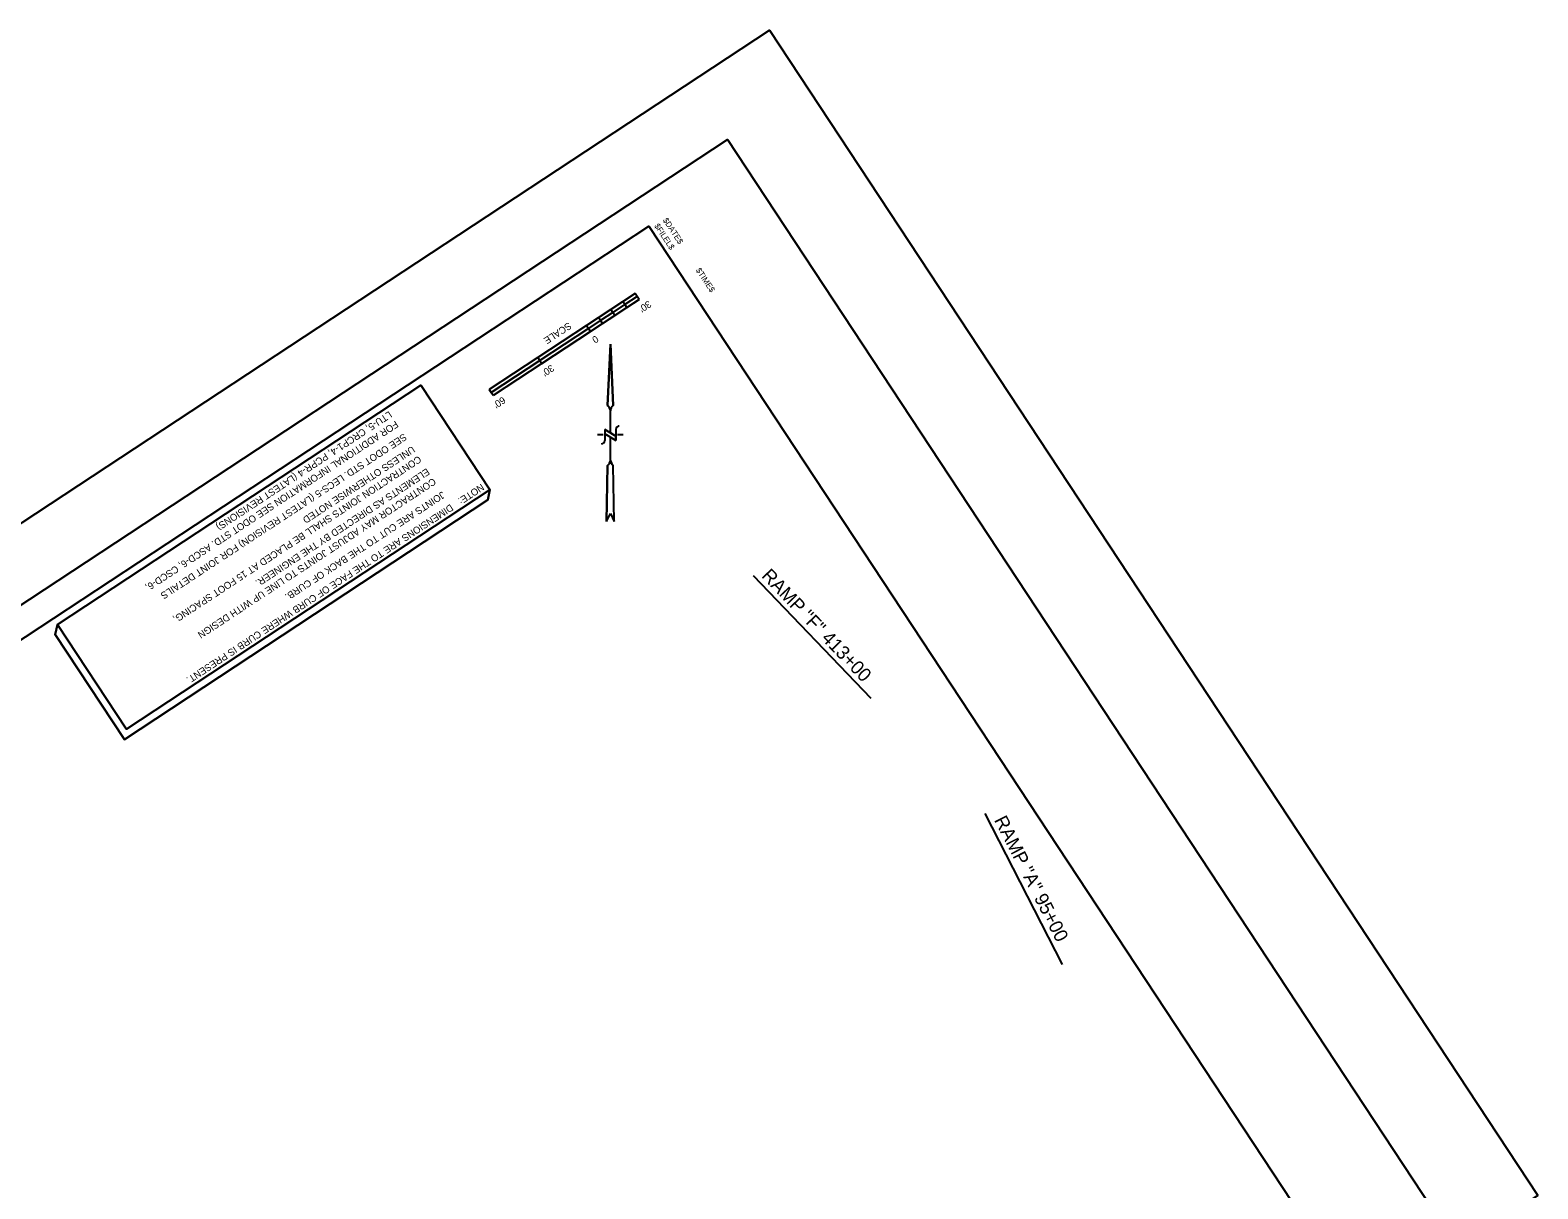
# Model space of a CAD drawing. Extents: x 2149232 to 2150530, y 142725 to 143920.
# Drawn here: x 2149753 to 2150530, y 143323 to 143920 of the extents above; entities that cross this region are included whole.
import ezdxf

# ---------------------------------------------------------------- set-up
doc = ezdxf.new("R2010")
doc.units = 0
for name, color, linetype in [('EX_Align_8_Leader', 7, 'Continuous'), ('PR_Align_1_Leader', 7, 'Continuous'), ('PR_Align_1_PI_Curve', 7, 'Continuous'), ('PR_Align_Ramp_A_PI_Curve', 7, 'Continuous'), ('PR_Align_Ramp_B_PC', 7, 'Continuous'), ('PR_Align_Ramp_B_PI', 7, 'Continuous'), ('PR_Align_Ramp_G', 7, 'Continuous'), ('PR_Align_Ramp_G_Leader', 7, 'Continuous'), ('PR_Align_Ramp_G_Txt', 7, 'Continuous')]:
    doc.layers.add(name, color=color, linetype=linetype)

msp = doc.modelspace()

# ---------------------------------------------------------------- linework, layer by layer
at = {"layer": 'EX_Align_8_Leader'}
for p, q in [((2150186.46, 143575.67), (2150125.85, 143638.92)), ((2150285.2, 143438.35), (2150245.3, 143516.34))]:
    msp.add_line(p, q, dxfattribs=at)
at = {"layer": 'PR_Align_1_PI_Curve'}
msp.add_lwpolyline([(2149989.95, 143683.24), (2149802.55, 143559.77), (2149766.96, 143613.78), (2149954.36, 143737.25)], close=True, dxfattribs=at)
msp.add_lwpolyline([(2149989.95, 143683.24), (2149988.88, 143678.05), (2149801.48, 143554.57), (2149765.89, 143608.59), (2149766.96, 143613.78)], dxfattribs=at)
at = {"layer": 'PR_Align_Ramp_A_PI_Curve'}
msp.add_lwpolyline([(2150475.65, 143312.82), (2149623.91, 142751.63), (2149260.79, 143302.75), (2150112.52, 143863.95)], close=True, dxfattribs=at)
at = {"layer": 'PR_Align_Ramp_B_PC'}
for p, q in [((2150064.81, 143784.61), (2149989.65, 143735.09)), ((2150066.87, 143781.48), (2150064.81, 143784.61)), ((2150066.87, 143781.48), (2149991.72, 143731.96)), ((2150058.54, 143780.48), (2150052.28, 143776.35)), ((2150054.34, 143773.22), (2150052.28, 143776.35)), ((2150054.34, 143773.22), (2150052.28, 143776.35)), ((2150052.28, 143776.35), (2150053.31, 143774.79)), ((2150059.57, 143778.92), (2150053.31, 143774.79)), ((2150053.31, 143774.79), (2150059.57, 143778.92)), ((2150060.61, 143777.35), (2150058.54, 143780.48)), ((2150059.57, 143778.92), (2150058.54, 143780.48)), ((2150065.84, 143783.04), (2150059.57, 143778.92)), ((2150065.84, 143783.04), (2150059.57, 143778.92)), ((2150059.57, 143778.92), (2150060.61, 143777.35)), ((2150060.61, 143777.35), (2150066.87, 143781.48)), ((2150066.87, 143781.48), (2150065.84, 143783.04)), ((2150046.02, 143772.23), (2150039.75, 143768.1)), ((2150047.05, 143770.66), (2150040.79, 143766.54)), ((2150040.79, 143766.54), (2150047.05, 143770.66)), ((2150048.08, 143769.1), (2150046.02, 143772.23)), ((2150047.05, 143770.66), (2150046.02, 143772.23)), ((2150053.31, 143774.79), (2150047.05, 143770.66)), ((2150053.31, 143774.79), (2150047.05, 143770.66)), ((2150047.05, 143770.66), (2150048.08, 143769.1)), ((2150048.08, 143769.1), (2150054.34, 143773.22)), ((2150054.34, 143773.22), (2150053.31, 143774.79)), ((2150040.79, 143766.54), (2149990.68, 143733.52)), ((2150040.79, 143766.54), (2150015.74, 143750.03)), ((2150016.77, 143748.46), (2150041.82, 143764.97)), ((2150039.75, 143768.1), (2150040.79, 143766.54)), ((2150039.75, 143768.1), (2150040.79, 143766.54)), ((2150040.79, 143766.54), (2150041.82, 143764.97)), ((2150041.82, 143764.97), (2150040.79, 143766.54)), ((2150014.7, 143751.6), (2149989.65, 143735.09)), ((2149990.68, 143733.52), (2150015.74, 143750.03)), ((2150014.7, 143751.6), (2150015.74, 143750.03)), ((2150015.74, 143750.03), (2150014.7, 143751.6)), ((2150015.74, 143750.03), (2150016.77, 143748.46)), ((2150015.74, 143750.03), (2150016.77, 143748.46)), ((2149990.68, 143733.52), (2149989.65, 143735.09)), ((2149989.65, 143735.09), (2149990.68, 143733.52)), ((2149991.72, 143731.96), (2149990.68, 143733.52))]:
    msp.add_line(p, q, dxfattribs=at)
at = {"layer": 'PR_Align_Ramp_B_PI'}
for p, q in [((2150050.65, 143726.77), (2150052.09, 143758.51)), ((2150052.09, 143758.51), (2150050.65, 143726.77)), ((2150052.09, 143758.51), (2150053.53, 143726.77)), ((2150053.53, 143726.77), (2150052.09, 143758.51)), ((2150052.09, 143712.74), (2150052.09, 143723.97)), ((2150054.97, 143711.01), (2150049.21, 143714.47)), ((2150049.21, 143714.47), (2150054.97, 143711.01)), ((2150049.21, 143714.47), (2150049.21, 143708.71)), ((2150052.09, 143712.74), (2150049.21, 143714.47)), ((2150049.21, 143714.47), (2150049.21, 143712.17)), ((2150054.97, 143714.47), (2150054.97, 143708.71)), ((2150048.35, 143711.59), (2150045.47, 143711.59)), ((2150054.97, 143708.71), (2150049.21, 143712.17)), ((2150054.97, 143711.01), (2150052.09, 143712.74)), ((2150052.09, 143698.64), (2150052.09, 143710.44)), ((2150054.97, 143708.71), (2150054.97, 143711.01)), ((2150058.71, 143711.59), (2150055.83, 143711.59)), ((2150050.07, 143666.97), (2150050.65, 143695.76)), ((2150050.65, 143695.76), (2150050.07, 143666.97)), ((2150054.1, 143666.97), (2150053.53, 143695.76)), ((2150054.1, 143666.97), (2150053.53, 143695.76)), ((2150050.07, 143666.97), (2150052.09, 143671)), ((2150050.07, 143666.97), (2150052.09, 143671)), ((2150052.09, 143671), (2150054.1, 143666.97)), ((2150052.09, 143671), (2150054.1, 143666.97))]:
    msp.add_line(p, q, dxfattribs=at)
for points in [[(2150049.21, 143712.17), (2150052.09, 143710.44), (2150054.97, 143708.71)], [(2150052.09, 143698.64), (2150052.09, 143698.64), (2150052.08, 143698.64)]]:
    msp.add_lwpolyline(points, dxfattribs=at)
for centre, radius, start, end in [((2150048.63, 143723.97), 3.45, 360, 54.38016), ((2150048.63, 143723.97), 3.45, 360, 54.38016), ((2150055.54, 143723.97), 3.45, 125.61984, 180), ((2150055.54, 143723.97), 3.45, 125.61984, 180), ((2150056.69, 143714.47), 1.73, 90, 180), ((2150047.48, 143708.71), 1.73, 270, 360), ((2150047.08, 143699.34), 5.06, 314.95671, 352.41889), ((2150047.08, 143699.34), 5.06, 314.95671, 352.059), ((2150057.1, 143699.34), 5.06, 187.58111, 225.04329), ((2150057.1, 143699.34), 5.06, 187.941, 225.04329)]:
    msp.add_arc(centre, radius, start, end, dxfattribs=at)
at = {"layer": 'PR_Align_Ramp_G'}
msp.add_line((2149988.88, 143678.05), (2149989.95, 143683.24), dxfattribs=at)
for points in [[(2149989.95, 143683.24), (2149802.55, 143559.77), (2149766.96, 143613.78)], [(2149766.96, 143613.78), (2149765.89, 143608.59), (2149801.48, 143554.57), (2149988.88, 143678.05)]]:
    msp.add_lwpolyline(points, dxfattribs=at)
at = {"layer": 'PR_Align_Ramp_G_Leader'}
msp.add_lwpolyline([(2150530.29, 143319.19), (2149628.45, 142724.98), (2149232.31, 143326.21), (2150134.15, 143920.41)], close=True, dxfattribs=at)
at = {"layer": 'PR_Align_Ramp_G_Txt'}
msp.add_lwpolyline([(2149282.82, 143299.31), (2150071.93, 143819.24), (2150418.55, 143293.16), (2149629.44, 142773.23)], close=True, dxfattribs=at)

# ---------------------------------------------------------------- texts
at = {"layer": 'PR_Align_1_Leader'}
for s, p in [('$DATE$', (2150079.01, 143822.38)), ('$FILEL$', (2150074.57, 143819.45)), ('$TIME$', (2150096.01, 143796.58))]:
    msp.add_text(s, height=3, rotation=303.38021, dxfattribs=at).set_placement(p)
at = {"layer": 'PR_Align_1_PI_Curve'}
for s, height, rotation, p in [('LTU-5, CRCP1-4, PCPR-4 (LATEST REVISIONS)', 3.6, 213.38021, (2149937.94, 143724.09)), ('FOR ADDITIONAL INFORMATION SEE ODOT STD. ASCD-6, CSCD-6,', 3.6, 213.38021, (2149941.24, 143719.07)), ('SEE ODOT STD. LECS-5 (LATEST REVISION) FOR JOINT DETAILS', 3.6, 213.38021, (2149945.56, 143712.52)), ('CONTRACTION JOINTS SHALL BE PLACED AT 15 FOOT SPACING,', 3.6, 213.38021, (2149953.11, 143701.05)), ('UNLESS OTHERWISE NOTED', 3.6, 213.38021, (2149949.8, 143706.07)), ('ELEMENTS AS DIRECTED BY THE ENGINEER.', 3.6, 213.38021, (2149957.35, 143694.62)), ('CONTRACTOR MAY ADJUST JOINTS TO LINE UP WITH DESIGN', 3.6, 213.38021, (2149960.66, 143689.6)), ('NOTE:', 3.6, 213.38021, (2149985.5, 143686.62)), ('DIMENSIONS ARE TO THE FACE OF CURB WHERE CURB IS PRESENT.', 3.6, 213.38021, (2149969.55, 143676.11)), ('JOINTS ARE CUT TO THE BACK OF CURB.', 3.6, 213.38021, (2149965.24, 143682.64)), ('RAMP "F" 413+00', 7, 313.81741, (2150129.62, 143638.54)), ('RAMP "A" 95+00', 7, 297.1314, (2150249.79, 143512.97))]:
    msp.add_text(s, height=height, rotation=rotation, dxfattribs=at).set_placement(p)
at = {"layer": 'PR_Align_Ramp_B_PC'}
for s, p in [("30'", (2150071.7, 143781.07)), ('SCALE', (2150030.49, 143769.9)), ('0', (2150044.46, 143763.12)), ("30'", (2150021.6, 143748.06)), ("60'", (2149996.55, 143731.55))]:
    msp.add_text(s, height=3.6, rotation=213.38021, dxfattribs=at).set_placement(p)

doc.saveas('drawing.dxf')
